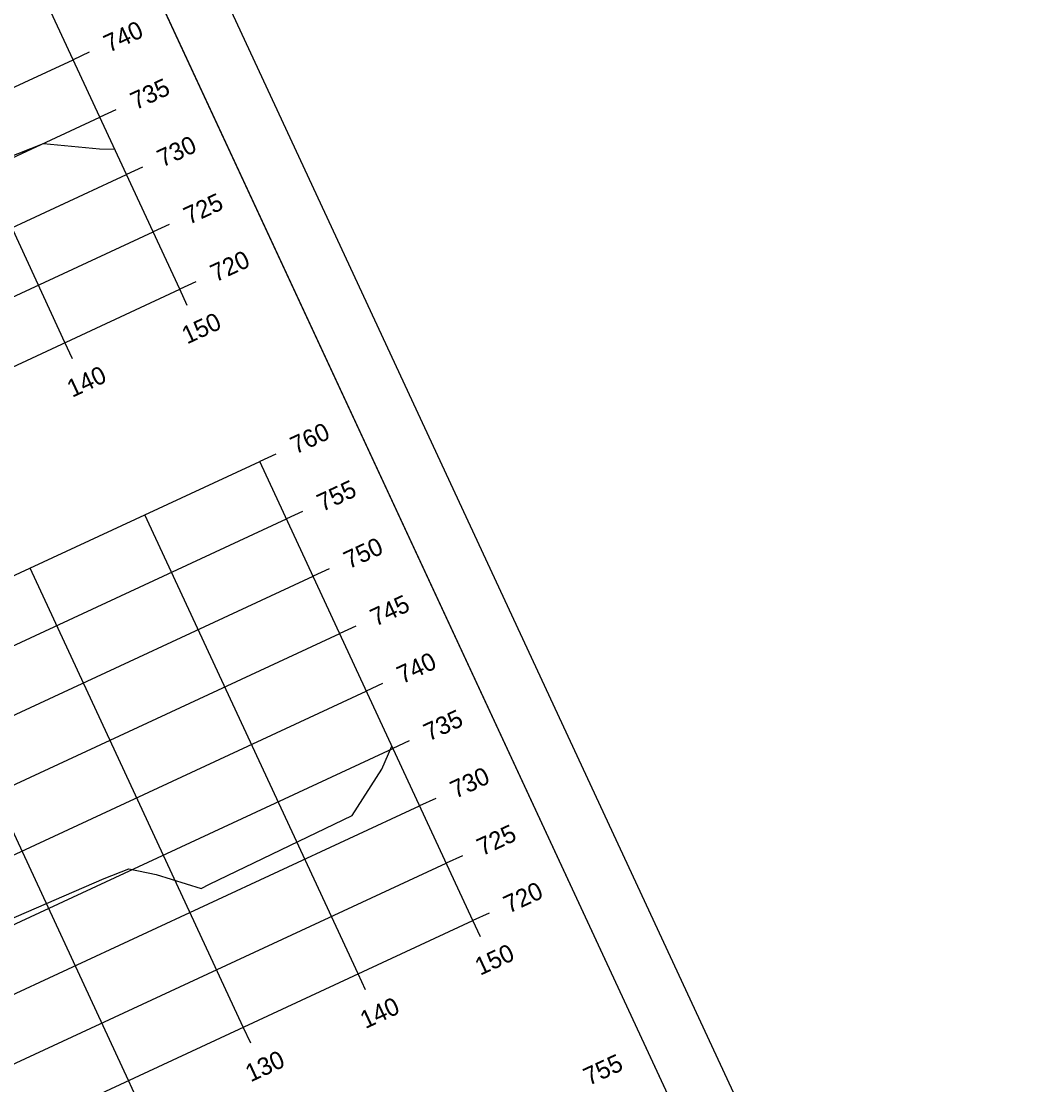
# Model space of a CAD drawing. Extents: x 1354696 to 1366163, y 660729 to 670380.
# Drawn here: x 1358996.6 to 1359075.2, y 666094.8 to 666178.8 of the extents above; entities that cross this region are included whole.
import ezdxf

# ---------------------------------------------------------------- set-up
doc = ezdxf.new("R2010")
doc.units = 0
for name, color, linetype in [('R_Axis', 7, 'Continuous'), ('R_Axis Annot', 7, 'Continuous'), ('R_Border', 7, 'Continuous'), ('R_Exist Surface', 7, 'Continuous'), ('R_Grid', 7, 'Continuous'), ('R_No Plot', 7, 'Continuous')]:
    doc.layers.add(name, color=color, linetype=linetype)

msp = doc.modelspace()

# ---------------------------------------------------------------- linework, layer by layer
at = {"layer": 'R_Axis'}
for p, q in [((1359009.12, 666157.609), (1358992.276, 666193.89)), ((1359001.968, 666176.339), (1359000.698, 666175.749)), ((1359004.073, 666171.804), (1359002.803, 666171.214)), ((1359006.179, 666167.269), (1359004.909, 666166.679)), ((1359008.284, 666162.734), (1359007.014, 666162.144)), ((1359010.39, 666158.199), (1359009.12, 666157.609)), ((1358737.016, 666031.279), (1359009.12, 666157.609)), ((1359009.709, 666156.339), (1359009.12, 666157.609)), ((1359000.639, 666152.128), (1359000.05, 666153.398)), ((1359016.706, 666144.594), (1359015.436, 666144.004)), ((1359032.281, 666107.723), (1359015.436, 666144.004)), ((1359018.812, 666140.058), (1359017.542, 666139.469)), ((1359020.917, 666135.523), (1359019.647, 666134.934)), ((1359023.023, 666130.988), (1359021.753, 666130.399)), ((1359025.128, 666126.453), (1359023.858, 666125.864)), ((1359027.234, 666121.918), (1359025.964, 666121.329)), ((1359029.339, 666117.383), (1359028.069, 666116.794)), ((1359031.445, 666112.848), (1359030.175, 666112.259)), ((1359033.55, 666108.313), (1359032.281, 666107.723)), ((1358760.176, 665981.393), (1359032.281, 666107.723)), ((1359032.87, 666106.454), (1359032.281, 666107.723)), ((1359023.8, 666102.243), (1359023.21, 666103.512)), ((1359014.73, 666098.032), (1359014.14, 666099.301)), ((1359005.66, 666093.821), (1359005.07, 666095.09))]:
    msp.add_line(p, q, dxfattribs=at)
at = {"layer": 'R_Border'}
msp.add_line((1359069.177, 666047.677), (1358982.657, 666234.032), dxfattribs=at)
at = {"layer": 'R_Exist Surface'}
for points in [[(1358995.356, 666167.941), (1358998.361, 666169.144), (1359002.771, 666168.699), (1359003.984, 666168.672)], [(1358995.419, 666107.701), (1359003.144, 666111.04), (1359005.082, 666111.81), (1359007.258, 666111.378), (1359010.804, 666110.259), (1359011.478, 666110.603), (1359022.749, 666116.035), (1359025.088, 666119.684), (1359025.883, 666121.503)]]:
    msp.add_lwpolyline(points, dxfattribs=at)
at = {"layer": 'R_Grid'}
for p, q in [((1359009.12, 666157.609), (1358992.276, 666193.89)), ((1359000.05, 666153.398), (1358983.206, 666189.679)), ((1358728.594, 666049.419), (1359000.698, 666175.749)), ((1358730.699, 666044.884), (1359002.803, 666171.214)), ((1358732.805, 666040.349), (1359004.909, 666166.679)), ((1358734.91, 666035.814), (1359007.014, 666162.144)), ((1358737.016, 666031.279), (1359009.12, 666157.609)), ((1358743.332, 666017.673), (1359015.436, 666144.004)), ((1359032.281, 666107.723), (1359015.436, 666144.004)), ((1359023.21, 666103.512), (1359006.366, 666139.793)), ((1358745.438, 666013.138), (1359017.542, 666139.469)), ((1359014.14, 666099.301), (1358997.296, 666135.582)), ((1358747.543, 666008.603), (1359019.647, 666134.934)), ((1359005.07, 666095.09), (1358988.226, 666131.371)), ((1358749.649, 666004.068), (1359021.753, 666130.399)), ((1358751.754, 665999.533), (1359023.858, 666125.864)), ((1358753.86, 665994.998), (1359025.964, 666121.329)), ((1358755.965, 665990.463), (1359028.069, 666116.794)), ((1358758.071, 665985.928), (1359030.175, 666112.259)), ((1358760.176, 665981.393), (1359032.281, 666107.723))]:
    msp.add_line(p, q, dxfattribs=at)
at = {"layer": 'R_No Plot'}
for points in [[(1358682.984, 666099.196), (1358985.328, 666239.566), (1359075.165, 666046.066), (1358772.821, 665905.696)], [(1358908.047, 666199.392), (1358925.842, 666207.654), (1358930.003, 666198.693), (1358944.616, 666205.478), (1358965.659, 666215.247), (1358977.625, 666189.759), (1358998.675, 666199.532), (1359069.177, 666047.677), (1358782.398, 665914.533), (1358695.878, 666100.888)]]:
    msp.add_lwpolyline(points, close=True, dxfattribs=at)

# ---------------------------------------------------------------- texts
at = {"layer": 'R_Axis Annot'}
for s, p in [('740', (1359003.532, 666176.294)), ('735', (1359005.638, 666171.759)), ('730', (1359007.743, 666167.223)), ('725', (1359009.849, 666162.688)), ('720', (1359011.954, 666158.153)), ('150', (1359009.694, 666153.245)), ('140', (1359000.624, 666149.034)), ('760', (1359018.271, 666144.548)), ('755', (1359020.376, 666140.013)), ('750', (1359022.482, 666135.478)), ('745', (1359024.587, 666130.943)), ('740', (1359026.693, 666126.408)), ('735', (1359028.798, 666121.873)), ('730', (1359030.904, 666117.338)), ('725', (1359033.009, 666112.803)), ('720', (1359035.115, 666108.268)), ('150', (1359032.854, 666103.359)), ('140', (1359023.784, 666099.148)), ('130', (1359014.714, 666094.937)), ('755', (1359041.431, 666094.662))]:
    msp.add_text(s, height=1.4, rotation=24.90417, dxfattribs=at).set_placement(p)

doc.saveas('drawing.dxf')
